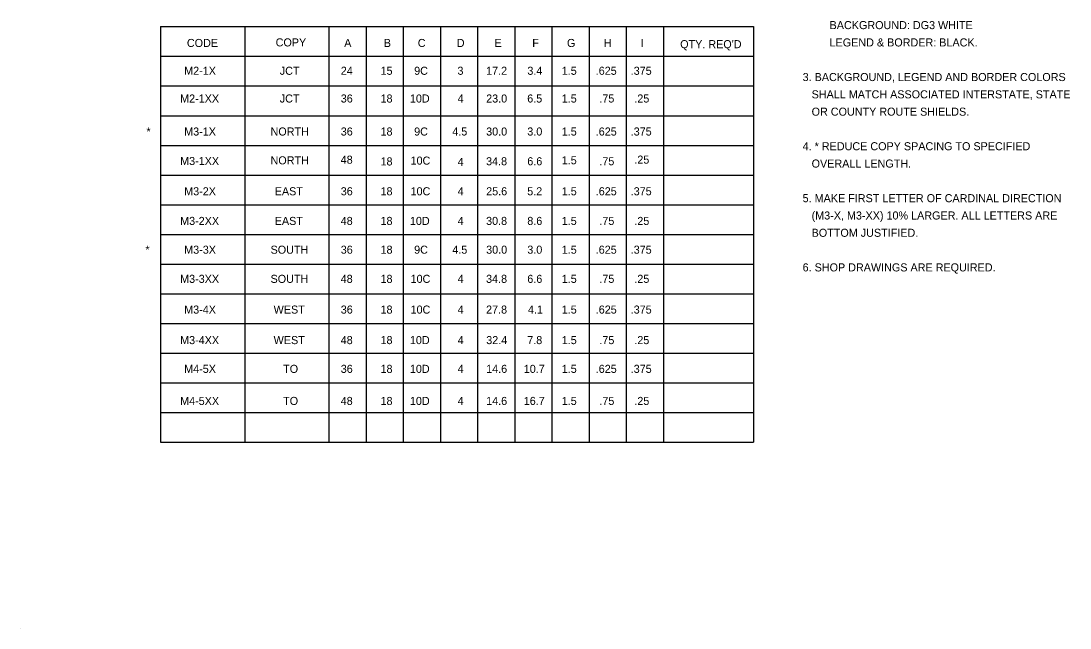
# Model space of a CAD drawing. Extents: x 60714 to 61340, y 8039 to 8429.
# Drawn here: x 60713.6 to 61077.8, y 8039 to 8249.9 of the extents above; entities that cross this region are included whole.
import ezdxf

# ---------------------------------------------------------------- set-up
doc = ezdxf.new("R2010")
doc.units = 0
for name, color, linetype in [('AdhocPoint_dp', 7, 'Continuous'), ('TextNotes', 7, 'Continuous'), ('TextTables', 7, 'Continuous')]:
    doc.layers.add(name, color=color, linetype=linetype)

msp = doc.modelspace()

# ---------------------------------------------------------------- linework, layer by layer
at = {"layer": 'AdhocPoint_dp'}
msp.add_line((60713.58, 8038.97), (60713.58, 8038.97), dxfattribs=at)
at = {"layer": 'TextTables'}
for p, q in [((60762.08, 8248), (60967.93, 8248)), ((60762.08, 8248), (60762.08, 8103.52)), ((60791.29, 8248), (60791.29, 8103.52)), ((60791.29, 8248), (60791.29, 8175.75)), ((60820.5, 8248), (60820.5, 8103.52)), ((60833.42, 8248), (60833.42, 8103.52)), ((60846.31, 8248), (60846.31, 8103.52)), ((60859.2, 8248), (60859.2, 8103.52)), ((60872.12, 8248), (60872.12, 8103.52)), ((60885.01, 8248), (60885.01, 8103.52)), ((60897.92, 8248), (60897.92, 8103.52)), ((60910.82, 8248), (60910.82, 8103.52)), ((60923.71, 8248), (60923.71, 8103.52)), ((60936.62, 8248), (60936.62, 8103.52)), ((60967.93, 8248), (60967.93, 8103.52)), ((60762.08, 8237.68), (60967.93, 8237.68)), ((60762.08, 8227.34), (60967.93, 8227.34)), ((60762.08, 8217.02), (60967.93, 8217.02)), ((60762.08, 8206.7), (60967.93, 8206.7)), ((60762.08, 8196.39), (60967.93, 8196.39)), ((60762.08, 8186.07), (60967.93, 8186.07)), ((60762.08, 8175.75), (60967.93, 8175.75)), ((60762.08, 8165.43), (60967.93, 8165.43)), ((60762.08, 8155.11), (60967.93, 8155.11)), ((60762.08, 8144.79), (60967.93, 8144.79)), ((60762.08, 8134.47), (60967.93, 8134.47)), ((60762.08, 8124.15), (60967.93, 8124.15)), ((60762.08, 8113.83), (60967.93, 8113.83)), ((60762.08, 8103.52), (60967.93, 8103.52))]:
    msp.add_line(p, q, dxfattribs=at)

# ---------------------------------------------------------------- texts
at = {"layer": 'TextNotes'}
for s, p in [('         BACKGROUND: DG3 WHITE', (60984.98, 8247.1)), ('         LEGEND & BORDER: BLACK.', (60984.98, 8241.08)), ('3. BACKGROUND, LEGEND AND BORDER COLORS', (60984.98, 8229.05)), ('   SHALL MATCH ASSOCIATED INTERSTATE, STATE', (60984.98, 8223.04)), ('   OR COUNTY ROUTE SHIELDS.', (60984.98, 8217.02)), ('4. * REDUCE COPY SPACING TO SPECIFIED', (60984.98, 8205)), ('   OVERALL LENGTH.', (60984.98, 8198.98)), ('5. MAKE FIRST LETTER OF CARDINAL DIRECTION ', (60984.98, 8186.95)), ('   (M3-X, M3-XX) 10% LARGER. ALL LETTERS ARE ', (60984.98, 8180.94)), ('   BOTTOM JUSTIFIED.', (60984.98, 8174.93)), ('6. SHOP DRAWINGS ARE REQUIRED.', (60984.98, 8162.9))]:
    msp.add_text(s, height=2.8, dxfattribs=at).set_placement(p)
at = {"layer": 'TextTables'}
for s, p in [('CODE', (60771.19, 8240.89)), ('COPY', (60802.01, 8241.09)), ('A', (60825.81, 8240.89)), ('B', (60839.55, 8240.89)), ('C', (60851.36, 8240.89)), ('D', (60864.89, 8240.89)), ('E', (60878, 8240.89)), ('F', (60891.11, 8240.89)), ('G', (60903.15, 8240.89)), ('H', (60915.88, 8240.89)), ('I', (60928.72, 8240.89)), ("QTY. REQ'D", (60942.46, 8240.47)), ('M2-1X', (60770.25, 8231.23)), ('JCT', (60803.44, 8231.23)), ('24', (60824.63, 8231.23)), ('15', (60838.43, 8231.23)), ('9C', (60850.1, 8231.23)), ('3', (60865.13, 8231.23)), ('17.2', (60875.07, 8231.23)), ('3.4', (60889.4, 8231.23)), ('1.5', (60901.34, 8231.23)), ('.625', (60913.14, 8231.23)), ('.375', (60925.28, 8231.23)), ('M2-1XX', (60768.84, 8221.59)), ('JCT', (60803.44, 8221.59)), ('36', (60824.61, 8221.59)), ('18', (60838.42, 8221.59)), ('10D', (60848.62, 8221.59)), ('23.0', (60875.1, 8221.59)), ('6.5', (60889.36, 8221.59)), ('.25', (60926.54, 8221.59)), ('4', (60865.19, 8221.59)), ('1.5', (60901.34, 8221.59)), ('.75', (60914.4, 8221.59)), ('*', (60757.15, 8210.12)), ('M3-1X', (60770.25, 8210.12)), ('NORTH', (60800.23, 8210.12)), ('36', (60824.61, 8210.12)), ('18', (60838.42, 8210.12)), ('9C', (60850.1, 8210.12)), ('4.5', (60863.34, 8210.12)), ('30.0', (60875.1, 8210.12)), ('3.0', (60889.38, 8210.12)), ('1.5', (60901.34, 8210.12)), ('.625', (60913.14, 8210.12)), ('.375', (60925.28, 8210.12)), ('M3-1XX', (60768.84, 8199.88)), ('NORTH', (60800.23, 8200.1)), ('48', (60824.59, 8200.34)), ('10C', (60848.85, 8200.01)), ('34.8', (60875.07, 8199.78)), ('6.6', (60889.38, 8199.78)), ('1.5', (60901.34, 8200.13)), ('.75', (60914.4, 8199.79)), ('.25', (60926.54, 8200.35)), ('18', (60838.42, 8199.72)), ('4', (60865.19, 8199.57)), ('M3-2X', (60770.25, 8189.35)), ('EAST', (60801.69, 8189.35)), ('36', (60824.61, 8189.35)), ('18', (60838.42, 8189.35)), ('10C', (60848.85, 8189.35)), ('4', (60865.19, 8189.35)), ('25.6', (60875.1, 8189.35)), ('5.2', (60889.35, 8189.35)), ('1.5', (60901.34, 8189.35)), ('.625', (60913.14, 8189.35)), ('.375', (60925.28, 8189.35)), ('M3-2XX', (60768.84, 8179.05)), ('EAST', (60801.69, 8179.05)), ('48', (60824.59, 8179.05)), ('18', (60838.42, 8179.05)), ('10D', (60848.62, 8179.05)), ('4', (60865.19, 8179.05)), ('30.8', (60875.07, 8179.05)), ('8.6', (60889.38, 8179.05)), ('1.5', (60901.34, 8179.05)), ('.75', (60914.4, 8179.05)), ('.25', (60926.54, 8179.05)), ('*', (60756.8, 8169.05)), ('M3-3X', (60770.25, 8169.05)), ('SOUTH', (60800.24, 8169.05)), ('36', (60824.61, 8169.05)), ('18', (60838.42, 8169.05)), ('9C', (60850.1, 8169.05)), ('4.5', (60863.34, 8169.05)), ('30.0', (60875.1, 8169.05)), ('3.0', (60889.38, 8169.05)), ('1.5', (60901.34, 8169.05)), ('.625', (60913.14, 8169.05)), ('.375', (60925.28, 8169.05)), ('M3-3XX', (60768.84, 8158.92)), ('SOUTH', (60800.24, 8158.92)), ('48', (60824.59, 8158.92)), ('18', (60838.42, 8158.92)), ('10C', (60848.85, 8158.92)), ('4', (60865.19, 8158.92)), ('34.8', (60875.07, 8158.92)), ('6.6', (60889.38, 8158.92)), ('1.5', (60901.34, 8158.92)), ('.75', (60914.4, 8158.92)), ('.25', (60926.54, 8158.92)), ('M3-4X', (60770.25, 8148.24)), ('WEST', (60801.31, 8148.24)), ('36', (60824.61, 8148.24)), ('18', (60838.42, 8148.24)), ('10C', (60848.85, 8148.24)), ('4', (60865.19, 8148.24)), ('27.8', (60875.07, 8148.24)), ('4.1', (60889.6, 8148.24)), ('1.5', (60901.34, 8148.24)), ('.625', (60913.14, 8148.24)), ('.375', (60925.28, 8148.24)), ('M3-4XX', (60768.84, 8137.63)), ('WEST', (60801.31, 8137.63)), ('48', (60824.59, 8137.63)), ('18', (60838.42, 8137.63)), ('10D', (60848.62, 8137.63)), ('4', (60865.19, 8137.63)), ('32.4', (60875.12, 8137.63)), ('7.8', (60889.36, 8137.63)), ('1.5', (60901.34, 8137.63)), ('.75', (60914.4, 8137.63)), ('.25', (60926.54, 8137.63)), ('M4-5X', (60770.25, 8127.64)), ('TO', (60804.61, 8127.64)), ('36', (60824.61, 8127.64)), ('18', (60838.42, 8127.64)), ('10D', (60848.62, 8127.64)), ('4', (60865.19, 8127.64)), ('14.6', (60875.1, 8127.64)), ('10.7', (60888.15, 8127.64)), ('1.5', (60901.34, 8127.64)), ('.625', (60913.14, 8127.64)), ('.375', (60925.28, 8127.64)), ('M4-5XX', (60768.84, 8116.49)), ('TO', (60804.61, 8116.49)), ('48', (60824.59, 8116.49)), ('18', (60838.42, 8116.49)), ('10D', (60848.62, 8116.49)), ('4', (60865.19, 8116.49)), ('14.6', (60875.1, 8116.49)), ('16.7', (60888.15, 8116.49)), ('1.5', (60901.34, 8116.49)), ('.75', (60914.4, 8116.49)), ('.25', (60926.54, 8116.49))]:
    msp.add_text(s, height=2.8, dxfattribs=at).set_placement(p)

doc.saveas('drawing.dxf')
